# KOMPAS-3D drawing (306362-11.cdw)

Referenced files in C:\Documents and Settings\Icedog\Рабочий стол\тау\рисунки\: выбор С0 и С1.JPG, кчх.JPG, годограф.JPG, Акульшин.JPG
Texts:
  КП 220301.072676.2011
  Расчет системы  автоматического регулирования температуры нагревательной печи
  Григорьев А.А.
  Текст на чертеже
  Размерные надписи
  Шероховатость
  Линия-выноска #1
  Линия-выноска #2
  Линия-выноска #3
  Отклонения формы и база
  Заголовок таблицы
  Ячейка таблицы
  Стрелка вида
  Обозначение изменения
  Фигурная скобка
  Номер узла
  Марка координационной оси
  VRCB
  Выносная надпись
  Обозначение узла
  Марка/позиционное обозначение с линией-выноской
  Марка/позиционное обозначение на линии
  Марка/позиционное обозначение без линии-выноски
  Кривые D-разбиения для
  парамеров ПИ регулятора
  Годограф комплексной частотной характеристики
  замкнутой системы относительно возмущающего
  воздействия
  Переходные процессы по возмущающему воздействию
  и смоделированный методом Акульшина
  рисунки\выбор С0 и С1.JPG
  рисунки\кчх.JPG
  рисунки\годограф.JPG
  рисунки\Акульшин.JPG
  Комплексно-частотная характеристика объекта (КЧХ)
  Расчет системы
  автоматического регулирования
  температуры нагревательной печи
  Кокуев А.Г.
  Переходные и частотные
  характеристики объекта.
  Выбор параметров регулятора
  АГТУ ДИА-41
  КП 220301.072676.2011-
Dimensions and other numbers on the sheet: 7; 1:1; 1; 0; 2; 3; 4; 5; 6; 8; 9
